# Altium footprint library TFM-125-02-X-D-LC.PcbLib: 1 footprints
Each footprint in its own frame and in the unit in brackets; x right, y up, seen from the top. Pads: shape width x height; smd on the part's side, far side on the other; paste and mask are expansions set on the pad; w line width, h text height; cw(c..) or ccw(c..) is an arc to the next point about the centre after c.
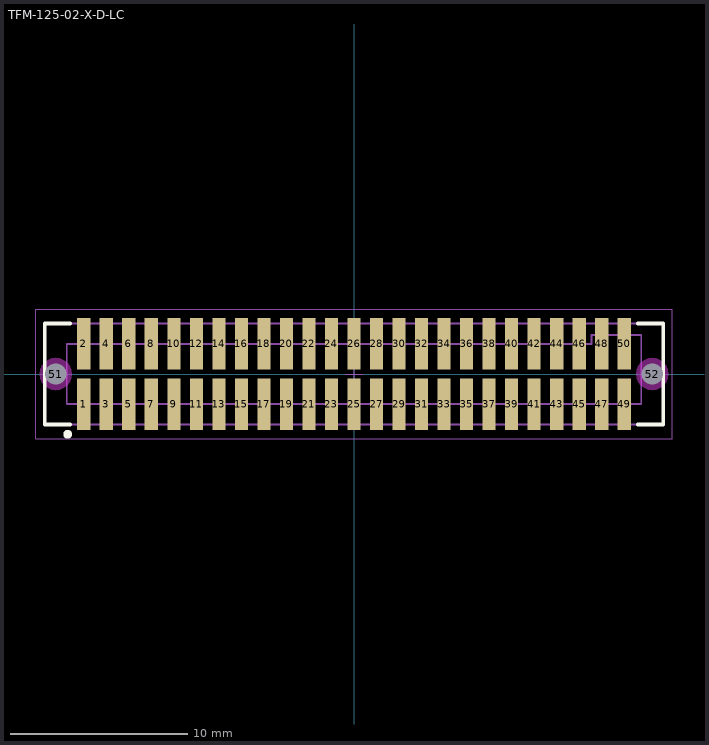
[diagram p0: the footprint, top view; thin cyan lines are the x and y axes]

## TFM-125-02-X-D-LC [mm] "1.27mm pitch, 50 pin, micro terminal strip; double row, w/locking clips, SMT"
height 5.72
pads (52):
  rect 0.75x2.9 smd mask+0: 1(-15.24,-1.714) 2(-15.24,1.714) 3(-13.97,-1.714) 4(-13.97,1.714) 5(-12.7,-1.714) 6(-12.7,1.714) 7(-11.43,-1.714) 8(-11.43,1.714) 9(-10.16,-1.714) 10(-10.16,1.714) 11(-8.89,-1.714) 12(-8.89,1.714) 13(-7.62,-1.714) 14(-7.62,1.714) 15(-6.35,-1.714) 16(-6.35,1.714) 17(-5.08,-1.714) 18(-5.08,1.714) 19(-3.81,-1.714) 20(-3.81,1.714) 21(-2.54,-1.714) 22(-2.54,1.714) 23(-1.27,-1.714) 24(-1.27,1.714) 25(0,-1.714) 26(0,1.714) 27(1.27,-1.714) 28(1.27,1.714) 29(2.54,-1.714) 30(2.54,1.714) 31(3.81,-1.714) 32(3.81,1.714) 33(5.08,-1.714) 34(5.08,1.714) 35(6.35,-1.714) 36(6.35,1.714) 37(7.62,-1.714) 38(7.62,1.714) 39(8.89,-1.714) 40(8.89,1.714) 41(10.16,-1.714) 42(10.16,1.714) 43(11.43,-1.714) 44(11.43,1.714) 45(12.7,-1.714) 46(12.7,1.714) 47(13.97,-1.714) 48(13.97,1.714) 49(15.24,-1.714) 50(15.24,1.714)
  round 1 hole 1.2 unplated mask+0: 51(-16.828,0) 52(16.828,0)
Top Overlay:
  circle w0.25: c-16.15,-3.4 r0.125
  lines w0.2: -16,-2.85 -17.45,-2.85 -17.45,2.85 -16,2.85 ; 16,-2.85 17.45,-2.85 17.45,2.85 16,2.85
Keep-Out Layer:
  pour cut-out: 17.735,0 17.705,0.235 17.614,0.454 17.47,0.642 17.282,0.786 17.063,0.877 16.828,0.908 16.593,0.877 16.374,0.786 16.186,0.642 16.042,0.454 15.951,0.235 15.92,0 15.951,-0.235 16.042,-0.454 16.186,-0.642 16.374,-0.786 16.593,-0.877 16.828,-0.908 17.063,-0.877 17.282,-0.786 17.47,-0.642 17.614,-0.454 17.705,-0.235
  pour cut-out: -15.92,0 -15.951,0.235 -16.042,0.454 -16.186,0.642 -16.374,0.786 -16.593,0.877 -16.828,0.908 -17.063,0.877 -17.282,0.786 -17.47,0.642 -17.614,0.454 -17.705,0.235 -17.735,0 -17.705,-0.235 -17.614,-0.454 -17.47,-0.642 -17.282,-0.786 -17.063,-0.877 -16.828,-0.908 -16.593,-0.877 -16.374,-0.786 -16.186,-0.642 -16.042,-0.454 -15.951,-0.235
Mechanical 13:
  circle w0.1: c-16.139,-3.366 r0.127
  lines w0.1: -17.45,-2.85 -17.45,2.85 17.45,2.85 17.45,-2.85 -17.45,-2.85 ; -16.2,-1.7 -16.2,1.7 13.4,1.7 13.4,2.2 16.2,2.2 16.2,-1.7 -16.2,-1.7
  text ".Designator" at 0,-0.127 h1.52
Mechanical 15:
  lines w0.05: -0.5,0 0.5,0 ; 0,-0.5 0,0.5 ; -17.95,-3.65 -17.95,3.65 17.95,3.65 17.95,-3.65 -17.95,-3.65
